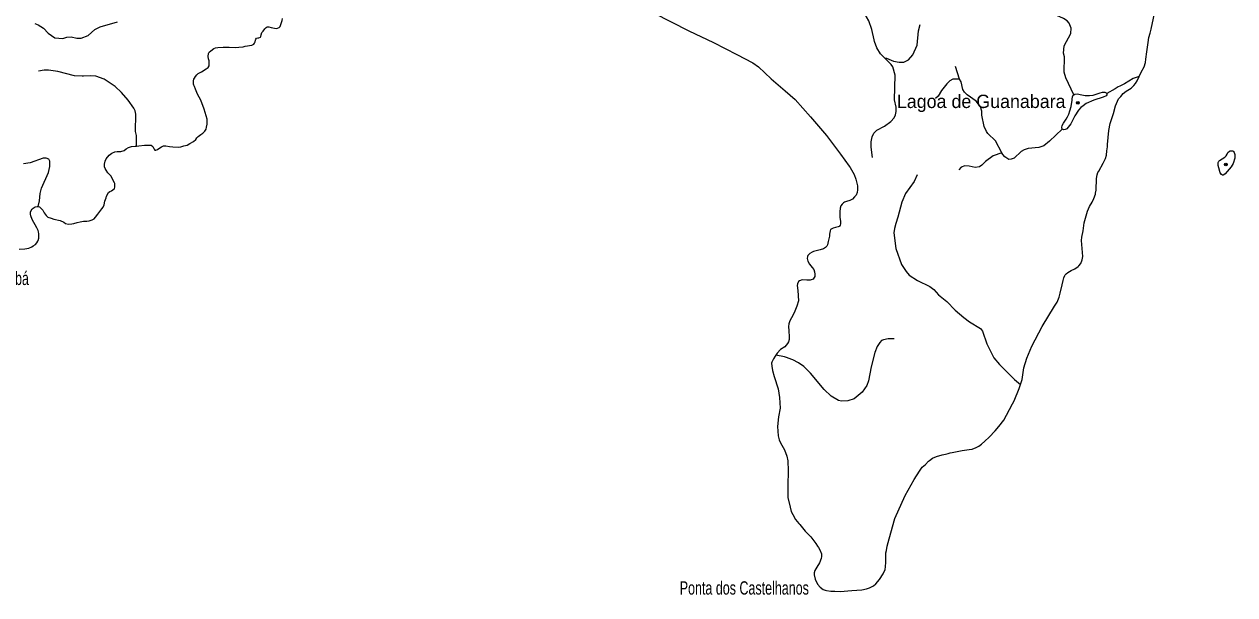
# Model space of a CAD drawing. Extents: x 317.8 to 344.1, y 7676.8 to 7704.8.
# Drawn here: x 325.56 to 332.82, y 7694.51 to 7697.93 of the extents above; entities that cross this region are included whole.
import ezdxf
from ezdxf.enums import TextEntityAlignment as Align

# ---------------------------------------------------------------- set-up
doc = ezdxf.new("R2010")
doc.units = 0
doc.header["$LTSCALE"] = 0.032
doc.header["$PDMODE"] = 32
doc.header["$PDSIZE"] = 0.016
doc.layers.add('2', color=7, linetype='Continuous', lineweight=25)
doc.layers.add('7', color=7, linetype='Continuous', lineweight=25)
doc.layers.add('54', color=7, linetype='Continuous')
doc.layers.add('61', color=7, linetype='Continuous')

msp = doc.modelspace()

# ---------------------------------------------------------------- linework, layer by layer
at = {"layer": '2'}
for points in [[(332.2426, 7697.6209), (332.2547, 7697.6465), (332.2733, 7697.6795), (332.2805, 7697.7054), (332.2836, 7697.726), (332.2888, 7697.7694), (332.296, 7697.8242), (332.3001, 7697.8541), (332.3084, 7697.881), (332.3146, 7697.9058), (332.329, 7697.9719), (332.3466, 7698.0556), (332.3673, 7698.1413), (332.3848, 7698.1702), (332.4138, 7698.2147), (332.4175, 7698.2188)], [(327.0865, 7697.916), (327.092, 7697.9207), (327.0974, 7697.9332), (327.1021, 7697.9503), (327.1044, 7697.9573), (327.1075, 7697.9682)], [(329.3311, 7698.0029), (329.5429, 7697.8954), (329.6917, 7697.8242), (329.8311, 7697.7529), (329.9262, 7697.7033), (329.9603, 7697.6785), (330.0367, 7697.6072), (330.0651, 7697.5827), (330.1206, 7697.5347), (330.1813, 7697.4822), (330.2733, 7697.3789), (330.3683, 7697.2663), (330.453, 7697.1547), (330.5047, 7697.0824), (330.5095, 7697.0744), (330.5336, 7697.0339), (330.5439, 7697.006), (330.5543, 7696.9657), (330.5543, 7696.9409), (330.5522, 7696.9254), (330.546, 7696.9089), (330.5357, 7696.8985), (330.5233, 7696.8861), (330.5078, 7696.8779), (330.4892, 7696.8717), (330.4757, 7696.8665), (330.4695, 7696.8624), (330.4623, 7696.8552), (330.4551, 7696.8459), (330.451, 7696.8304), (330.4489, 7696.8087), (330.4489, 7696.7756), (330.453, 7696.7529), (330.453, 7696.7374), (330.451, 7696.7291), (330.4468, 7696.724), (330.4438, 7696.7221), (330.4386, 7696.7188), (330.4231, 7696.7147), (330.4086, 7696.7116), (330.3931, 7696.7023), (330.39, 7696.695), (330.3869, 7696.6744), (330.3856, 7696.6624), (330.3848, 7696.6547), (330.3776, 7696.631), (330.3735, 7696.6103), (330.3704, 7696.6041), (330.3631, 7696.5948), (330.3497, 7696.5866), (330.3311, 7696.5814), (330.3146, 7696.5773), (330.2908, 7696.5711), (330.2815, 7696.5669), (330.2681, 7696.5597), (330.2567, 7696.5473), (330.2536, 7696.5411), (330.2526, 7696.5297), (330.2557, 7696.5142), (330.266, 7696.4957), (330.2815, 7696.476), (330.2929, 7696.4626), (330.297, 7696.4492), (330.2991, 7696.4347), (330.2981, 7696.4213), (330.295, 7696.4151), (330.2877, 7696.4058), (330.2826, 7696.4027), (330.2712, 7696.3996), (330.2505, 7696.3996), (330.2216, 7696.4006), (330.2061, 7696.3954), (330.201, 7696.3903), (330.1948, 7696.3779), (330.1927, 7696.3676), (330.1968, 7696.3366), (330.201, 7696.2746), (330.1906, 7696.2436), (330.1751, 7696.2033), (330.1576, 7696.1723), (330.1483, 7696.1547), (330.1431, 7696.1382), (330.141, 7696.1207)], [(326.2307, 7697.2038), (326.2465, 7697.2059), (326.2792, 7697.209), (326.2939, 7697.209), (326.3079, 7697.209), (326.3157, 7697.2098), (326.3204, 7697.2082), (326.3297, 7697.2005), (326.3375, 7697.1849), (326.3406, 7697.1795), (326.3437, 7697.1787), (326.3476, 7697.1787), (326.3577, 7697.1841), (326.3709, 7697.1927), (326.3818, 7697.1989), (326.3935, 7697.2043), (326.4083, 7697.2059), (326.4293, 7697.202), (326.4503, 7697.1989), (326.4806, 7697.1973), (326.4969, 7697.1997), (326.5164, 7697.2043), (326.5358, 7697.2098), (326.5514, 7697.2183), (326.5732, 7697.2308), (326.5864, 7697.2432), (326.5942, 7697.2533), (326.6004, 7697.2603), (326.6167, 7697.2736), (326.63, 7697.2821), (326.6416, 7697.2922), (326.6486, 7697.3055), (326.6517, 7697.3171), (326.6548, 7697.3358), (326.6556, 7697.3537), (326.6548, 7697.3653), (326.6377, 7697.426), (326.6175, 7697.4781), (326.5973, 7697.5147), (326.5848, 7697.545), (326.5786, 7697.5614), (326.5755, 7697.5684), (326.5739, 7697.5754), (326.5724, 7697.5847), (326.5724, 7697.5956), (326.5755, 7697.6049), (326.5786, 7697.6111), (326.5848, 7697.6212), (326.5934, 7697.6314), (326.6019, 7697.6384), (326.6214, 7697.6493), (326.6494, 7697.6664), (326.6556, 7697.671), (326.6618, 7697.6757), (326.6665, 7697.6843), (326.6673, 7697.692), (326.6681, 7697.7045), (326.6673, 7697.7154), (326.6634, 7697.7263), (326.6611, 7697.741), (326.6626, 7697.7581), (326.6673, 7697.7675), (326.6766, 7697.776), (326.6953, 7697.79), (326.7054, 7697.7939), (326.7186, 7697.7947), (326.7505, 7697.797), (326.7878, 7697.7963), (326.8252, 7697.7947), (326.8454, 7697.797), (326.8711, 7697.7986), (326.8827, 7697.8025), (326.9232, 7697.8087), (326.9349, 7697.8141), (326.9395, 7697.8204), (326.9434, 7697.8297), (326.9457, 7697.839), (326.9473, 7697.846), (326.9512, 7697.8515), (326.9597, 7697.853), (326.9652, 7697.853), (326.9745, 7697.8577), (326.9776, 7697.8608), (326.9792, 7697.8709), (326.9839, 7697.8842), (326.9909, 7697.8935), (327.0002, 7697.9075), (327.0087, 7697.916), (327.0142, 7697.9184), (327.0251, 7697.9192), (327.0399, 7697.9153), (327.0585, 7697.9106), (327.0718, 7697.9098), (327.0772, 7697.9114), (327.0865, 7697.916)], [(331.5323, 7695.7739), (331.5419, 7695.8025), (331.5512, 7695.8727), (331.5687, 7695.9306), (331.5997, 7696.0039), (331.6607, 7696.1217), (331.735, 7696.2426), (331.7505, 7696.2663), (331.764, 7696.2973), (331.7691, 7696.3221), (331.7815, 7696.3707), (331.7877, 7696.3975), (331.7919, 7696.414), (331.797, 7696.4275), (331.7991, 7696.4306), (331.8043, 7696.4378), (331.8146, 7696.4461), (331.8352, 7696.4564), (331.8569, 7696.4678), (331.8766, 7696.4812), (331.8807, 7696.4853), (331.8931, 7696.4988), (331.9014, 7696.5215), (331.9045, 7696.5411), (331.8983, 7696.6124), (331.8962, 7696.6372), (331.8993, 7696.6578), (331.9076, 7696.6961), (331.9138, 7696.7436), (331.9324, 7696.8128), (331.9458, 7696.8417), (331.9613, 7696.8676), (331.9716, 7696.8892), (331.9809, 7696.9151), (331.9819, 7696.9202), (331.985, 7696.9388), (331.9871, 7697.0091), (331.9902, 7697.0318), (331.9954, 7697.0442), (332.0016, 7697.0535), (332.0274, 7697.101), (332.0419, 7697.1289), (332.047, 7697.1496), (332.0491, 7697.1744), (332.0532, 7697.1992), (332.0532, 7697.2136), (332.0615, 7697.2963), (332.0687, 7697.3397), (332.0883, 7697.3985), (332.1007, 7697.445), (332.1193, 7697.4863), (332.1328, 7697.5018), (332.1472, 7697.5184), (332.1658, 7697.5328), (332.1947, 7697.5514), (332.2102, 7697.5669), (332.2206, 7697.5793), (332.2309, 7697.5959), (332.2426, 7697.6209)], [(331.7809, 7697.305), (331.7794, 7697.3142), (331.7817, 7697.3279), (331.7893, 7697.3417), (331.8054, 7697.3661), (331.813, 7697.3791), (331.8206, 7697.3944), (331.8275, 7697.4158), (331.8344, 7697.4418), (331.8405, 7697.48), (331.8413, 7697.4846), (331.8436, 7697.4983), (331.8474, 7697.5083), (331.8504, 7697.5113)], [(332.0491, 7697.5197), (332.0499, 7697.5113), (332.0453, 7697.506), (332.0262, 7697.4968), (331.9704, 7697.4785), (331.9253, 7697.4586), (331.9062, 7697.4456), (331.8925, 7697.4342), (331.8787, 7697.4196), (331.8581, 7697.3845), (331.8329, 7697.3371), (331.8176, 7697.3165), (331.8092, 7697.3081), (331.8046, 7697.305), (331.8, 7697.3027), (331.7908, 7697.302), (331.7863, 7697.3027), (331.7809, 7697.305)], [(331.8504, 7697.5113), (331.8566, 7697.5151), (331.8703, 7697.5167), (331.8993, 7697.5106), (331.92, 7697.5075), (331.9444, 7697.5067), (331.9673, 7697.5098), (331.9727, 7697.5113), (331.9903, 7697.5167), (332.0094, 7697.5236), (332.0231, 7697.5266), (332.0361, 7697.5266), (332.0445, 7697.5236), (332.0491, 7697.5197)], [(325.6413, 7696.8411), (325.6499, 7696.8388), (325.6569, 7696.8325), (325.6693, 7696.8201), (325.6787, 7696.8038), (325.6896, 7696.7867), (325.7005, 7696.7773), (325.7199, 7696.7703), (325.737, 7696.7657), (325.7736, 7696.7563), (325.7954, 7696.7462), (325.8062, 7696.74), (325.8241, 7696.7353), (325.8436, 7696.7369), (325.856, 7696.7384), (325.8762, 7696.7454), (325.8949, 7696.7501), (325.9144, 7696.7524), (325.933, 7696.754), (325.947, 7696.7555), (325.9665, 7696.7602), (325.9781, 7696.768), (325.9859, 7696.7773), (325.9991, 7696.7952), (326.0116, 7696.8115), (326.024, 7696.8271), (326.031, 7696.8364), (326.038, 7696.852), (326.0419, 7696.8722), (326.0489, 7696.894), (326.052, 7696.9033), (326.0645, 7696.9251), (326.0723, 7696.9313), (326.0816, 7696.9352), (326.0901, 7696.9407), (326.0979, 7696.9469), (326.0995, 7696.9484), (326.101, 7696.957), (326.1018, 7696.964), (326.1018, 7696.9718), (326.1018, 7696.9788), (326.1003, 7696.9827), (326.0769, 7697.0247), (326.059, 7697.0441), (326.0497, 7697.0597), (326.0435, 7697.0698), (326.0404, 7697.0799), (326.0396, 7697.0954), (326.0435, 7697.1141), (326.0497, 7697.1266), (326.0684, 7697.1491), (326.0839, 7697.1616), (326.1018, 7697.1693), (326.115, 7697.1709), (326.1368, 7697.1717), (326.1578, 7697.1771), (326.1703, 7697.1865), (326.1843, 7697.195), (326.2022, 7697.2012), (326.2232, 7697.2028), (326.2307, 7697.2038)], [(325.5278, 7696.5844), (325.5628, 7696.5868), (325.5869, 7696.5922), (325.6048, 7696.5992), (325.6126, 7696.6046), (325.6258, 7696.614), (325.6343, 7696.6225), (325.6406, 7696.6326), (325.6421, 7696.6373), (325.6452, 7696.6513), (325.6468, 7696.6638), (325.6468, 7696.677), (325.6445, 7696.6886), (325.6413, 7696.698), (325.6351, 7696.7135), (325.6071, 7696.7633), (325.5978, 7696.7859), (325.5955, 7696.7952), (325.5955, 7696.8069), (325.6009, 7696.8178), (325.6071, 7696.8255), (325.6126, 7696.831), (325.625, 7696.8388), (325.6359, 7696.8411), (325.6413, 7696.8411)], [(330.141, 7696.1207), (330.1431, 7696.0948), (330.1441, 7696.0587), (330.1441, 7696.0442), (330.141, 7696.0297), (330.1348, 7696.0184)], [(330.1348, 7696.0184), (330.1183, 7695.9988), (330.0935, 7695.9833), (330.0718, 7695.9605), (330.0637, 7695.9487)], [(330.0637, 7695.9487), (330.0605, 7695.944), (330.0501, 7695.9275), (330.0398, 7695.9078), (330.0388, 7695.9006), (330.0398, 7695.8831), (330.0439, 7695.8572), (330.0543, 7695.8221), (330.0791, 7695.7477), (330.0873, 7695.695), (330.0915, 7695.631), (330.0801, 7695.5793), (330.0749, 7695.5204), (330.0791, 7695.4657), (330.0842, 7695.4409), (330.0935, 7695.4233), (330.1162, 7695.381), (330.1307, 7695.3438), (330.1359, 7695.3149), (330.1379, 7695.255), (330.1369, 7695.1682), (330.1369, 7695.0959), (330.1503, 7695.038), (330.1565, 7695.0112), (330.1658, 7694.9926), (330.1834, 7694.9636), (330.202, 7694.9399), (330.2084, 7694.9325), (330.2412, 7694.8944), (330.2753, 7694.8603), (330.3053, 7694.82), (330.3153, 7694.8036), (330.3198, 7694.7963), (330.3291, 7694.7808), (330.3384, 7694.757), (330.3384, 7694.7415), (330.3373, 7694.7302), (330.327, 7694.7033), (330.3105, 7694.6775), (330.2981, 7694.6578), (330.2939, 7694.6434), (330.295, 7694.631), (330.3001, 7694.6052), (330.3136, 7694.5762), (330.3301, 7694.5566), (330.3476, 7694.5432), (330.3609, 7694.54), (330.3693, 7694.538), (330.3941, 7694.5339), (330.4184, 7694.5326), (330.451, 7694.5308), (330.5212, 7694.538), (330.5801, 7694.5421), (330.609, 7694.5483), (330.6255, 7694.5525), (330.6503, 7694.5659), (330.6648, 7694.5773), (330.6855, 7694.6031), (330.7072, 7694.6372), (330.7195, 7694.664), (330.7226, 7694.6795), (330.7247, 7694.7074), (330.7247, 7694.7632), (330.7278, 7694.7777), (330.733, 7694.8025), (330.7433, 7694.8479), (330.7784, 7694.9698), (330.8404, 7695.1083), (330.8931, 7695.2043), (330.9262, 7695.2539), (330.9427, 7695.2766), (330.9428, 7695.2768), (330.9613, 7695.2942), (330.9797, 7695.3127), (330.985, 7695.318), (331.0036, 7695.3314), (331.0274, 7695.3407), (331.0625, 7695.351), (331.0825, 7695.3559), (331.0982, 7695.3598), (331.1099, 7695.3627), (331.1214, 7695.3655), (331.1813, 7695.3769), (331.2247, 7695.3836), (331.2412, 7695.3862), (331.265, 7695.3954), (331.2815, 7695.4027), (331.297, 7695.4151), (331.3167, 7695.4326), (331.3445, 7695.4574), (331.3794, 7695.4954), (331.4024, 7695.5204), (331.4313, 7695.5597), (331.4478, 7695.5886), (331.4843, 7695.6581)], [(331.4843, 7695.6581), (331.4933, 7695.6754), (331.5243, 7695.7498), (331.5323, 7695.7739)]]:
    msp.add_lwpolyline(points, dxfattribs=at)
msp.add_lwpolyline([(332.8162, 7697.1307), (332.8059, 7697.0998), (332.7945, 7697.0797), (332.782, 7697.0661), (332.7701, 7697.052), (332.7587, 7697.0367), (332.7511, 7697.0302), (332.7473, 7697.0291), (332.7429, 7697.0291), (332.7375, 7697.0335), (332.7288, 7697.0438), (332.7201, 7697.0731), (332.7163, 7697.0867), (332.7163, 7697.097), (332.7174, 7697.1057), (332.7212, 7697.1133), (332.7244, 7697.1166), (332.7396, 7697.1275), (332.7559, 7697.1372), (332.7646, 7697.1454), (332.7706, 7697.1557), (332.7755, 7697.1649), (332.7842, 7697.1731), (332.7891, 7697.1753), (332.7967, 7697.1758), (332.8037, 7697.1742), (332.8092, 7697.1704), (332.8124, 7697.1644), (332.8157, 7697.1541), (332.8162, 7697.147)], close=True, dxfattribs=at)
msp.add_point((331.8758, 7697.4634), dxfattribs=at)
at = {"layer": '54'}
msp.add_point((332.7622, 7697.0936), dxfattribs=at)
at = {"layer": '7'}
msp.add_line((331.1657, 7697.6048), (331.1411, 7697.6818), dxfattribs=at)
for points in [[(330.7178, 7697.7308), (330.6931, 7697.7578), (330.6708, 7697.794), (330.6556, 7697.8302), (330.6532, 7697.8417), (330.6402, 7697.9038), (330.6225, 7697.9557), (330.6088, 7697.9796), (330.588, 7698.0011), (330.5453, 7698.0338), (330.4827, 7698.0755), (330.3888, 7698.1527), (330.3546, 7698.1749), (330.2399, 7698.2299), (330.1857, 7698.2415), (330.1407, 7698.2419)], [(331.8504, 7697.5113), (331.8025, 7697.6137), (331.7942, 7697.6463), (331.7958, 7697.7392), (331.7892, 7697.7618), (331.7942, 7697.8055), (331.8335, 7697.8787), (331.8349, 7697.911), (331.8241, 7697.9419), (331.8112, 7697.9554), (331.7901, 7697.9694), (331.6523, 7698.0316), (331.6276, 7698.0338), (331.5636, 7698.0289), (331.4919, 7698.033)], [(325.6229, 7697.9383), (325.6428, 7697.9309), (325.6732, 7697.9108), (325.7026, 7697.8807), (325.7429, 7697.8526), (325.7902, 7697.8496), (325.8149, 7697.8568), (325.8396, 7697.8592), (325.8736, 7697.8512), (325.9, 7697.8512), (325.9412, 7697.868), (325.9824, 7697.9025), (326.0138, 7697.9182), (326.1175, 7697.9487)], [(330.7178, 7697.7308), (330.7285, 7697.7312), (330.7709, 7697.7139), (330.8038, 7697.7061), (330.8322, 7697.7063), (330.8609, 7697.7208), (330.8864, 7697.7512), (330.9122, 7697.8094), (330.9206, 7697.8946), (330.9304, 7697.9327)], [(330.6435, 7697.1357), (330.6361, 7697.1976), (330.6356, 7697.2301), (330.6423, 7697.2596), (330.6515, 7697.2802), (330.6697, 7697.2983), (330.7158, 7697.3235), (330.7547, 7697.3504), (330.7741, 7697.3734), (330.7822, 7697.3907), (330.7868, 7697.4119), (330.786, 7697.4363), (330.7754, 7697.4803), (330.781, 7697.6294), (330.7652, 7697.6799), (330.7562, 7697.6935), (330.7178, 7697.7308)], [(326.2307, 7697.2038), (326.2309, 7697.2671), (326.2261, 7697.2902), (326.2268, 7697.3946), (326.2241, 7697.4142), (326.2156, 7697.4319), (326.1816, 7697.48), (326.1421, 7697.5259), (326.1041, 7697.5616), (326.0375, 7697.6055), (325.9871, 7697.6228), (325.9567, 7697.6246), (325.9141, 7697.6225), (325.9055, 7697.6221), (325.8606, 7697.6254), (325.7605, 7697.6517), (325.7035, 7697.6588), (325.6784, 7697.6588), (325.645, 7697.6532)], [(331.42, 7697.1632), (331.3816, 7697.2361), (331.3356, 7697.2795), (331.3273, 7697.2912), (331.3144, 7697.3216), (331.3003, 7697.3887), (331.3002, 7697.4132), (331.292, 7697.4393), (331.2647, 7697.4727), (331.2119, 7697.5105), (331.1949, 7697.5263), (331.1859, 7697.543), (331.175, 7697.5888), (331.1657, 7697.6048), (331.1262, 7697.605), (331.1087, 7697.5953), (331.0897, 7697.5777), (331.0575, 7697.5364), (331.0376, 7697.5037), (331.0212, 7697.4883)], [(332.2426, 7697.6209), (332.2066, 7697.6099), (332.1541, 7697.5763), (332.1269, 7697.5633), (332.117, 7697.5585), (332.1, 7697.5479), (332.0491, 7697.5197)], [(331.7809, 7697.305), (331.7044, 7697.2333), (331.671, 7697.206), (331.6414, 7697.1944), (331.5781, 7697.1886), (331.5529, 7697.182), (331.5356, 7697.1712), (331.4929, 7697.1319), (331.4765, 7697.1247), (331.462, 7697.1227), (331.4374, 7697.1387), (331.4256, 7697.1525), (331.42, 7697.1632)], [(331.42, 7697.1632), (331.3671, 7697.146), (331.3226, 7697.1113), (331.3005, 7697.0893), (331.2849, 7697.08), (331.2602, 7697.0761), (331.2231, 7697.0835), (331.1976, 7697.085), (331.1762, 7697.0766), (331.1626, 7697.0607)], [(325.6413, 7696.8411), (325.6499, 7696.8746), (325.6534, 7696.9185), (325.6612, 7696.9503), (325.7031, 7697.0456), (325.7117, 7697.081), (325.7125, 7697.1131), (325.7051, 7697.1248), (325.6904, 7697.1305), (325.6718, 7697.1306), (325.5949, 7697.1037), (325.5534, 7697.0978)], [(330.9124, 7697.0313), (330.8935, 7696.9914), (330.842, 7696.9184), (330.8193, 7696.8671), (330.7967, 7696.7764), (330.7848, 7696.7386), (330.7755, 7696.7093), (330.7722, 7696.6822), (330.7836, 7696.5892), (330.8189, 7696.4936), (330.8451, 7696.4503), (330.864, 7696.4302), (330.9131, 7696.3974), (330.9873, 7696.3604), (331.0126, 7696.3433), (331.0408, 7696.3111), (331.0902, 7696.2714), (331.1403, 7696.219), (331.1917, 7696.1749), (331.2263, 7696.1496), (331.2913, 7696.1094), (331.3027, 7696.0931), (331.3301, 7696.0173), (331.372, 7695.9342), (331.4049, 7695.8941), (331.4959, 7695.8038), (331.5323, 7695.7739)], [(330.7747, 7696.0476), (330.739, 7696.0467), (330.7092, 7696.0418), (330.6986, 7696.0367), (330.6872, 7696.0248), (330.6727, 7696.0016), (330.6589, 7695.9644), (330.6361, 7695.8799), (330.6205, 7695.7952), (330.6102, 7695.7677), (330.5819, 7695.7278), (330.5337, 7695.6883), (330.4966, 7695.6763), (330.4584, 7695.6742), (330.4403, 7695.6765), (330.3958, 7695.7038), (330.3554, 7695.743), (330.272, 7695.8411), (330.2318, 7695.8804), (330.1998, 7695.9038), (330.1668, 7695.9206), (330.1609, 7695.9236), (330.1288, 7695.9355), (330.1169, 7695.9399), (330.0637, 7695.9487)]]:
    msp.add_lwpolyline(points, dxfattribs=at)

# ---------------------------------------------------------------- texts
at = {"layer": '61'}
msp.add_text('Lagoa de Guanabara', height=0.08, dxfattribs=at).set_placement((331.8016, 7697.4319), align=Align.RIGHT)
at = {"layer": '61', "width": 0.7}
msp.add_text('Ponta do Ubá', height=0.08, dxfattribs=at).set_placement((325.1287, 7696.3702))
msp.add_text('Ponta dos Castelhanos', height=0.08, dxfattribs=at).set_placement((330.2628, 7694.5128), align=Align.RIGHT)

doc.saveas('drawing.dxf')
